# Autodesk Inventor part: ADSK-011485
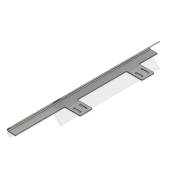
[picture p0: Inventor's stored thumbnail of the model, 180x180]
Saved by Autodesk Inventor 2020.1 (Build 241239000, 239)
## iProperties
Created: 2000-01
Part Number: ADSK-011485
Material: 1.0312 DC05
Description: FSHTPH,SS,CP,01,038,019,230,135,PLOW,END_TAB
Document SubType Name: Tôlerie
Designer: sspink
Density: 1 g/cm^3
Sheet Metal Rule: Stahlblech 1.0312 - DC05 -   3.0 mm
Appearance: Stahl
Mass: 159.002 g
Surface Area: 1116.27 cm^2
Volume: 159.002 cm^3
Flat Pattern Width: 58.38 cm
Flat Pattern Length: 15.7693 cm
Flat Pattern Area: 920.615 cm^2
Sheet Metal Width: 583,800 mm
Sheet Metal Length: 157,693 mm
Sheet Metal Area: 92061,453 mm^2
Control State: 0
Master: False
Checked Out: False
Shininess: 57.0
Length Units: 11269
Angle Units: 11279
Time Units: 11290
Mass Units: 11283
Length Display Precision: 3
Angle Display Precision: 2
Compacted: True
CUTLENGTH: 6.20 X 23.00 (143 SI)
MATERIAL DESC: SHEET,S/S, 11 GA
MATERIAL_NUMBER: A084638
G_L: 157,7x583,8 mm
Thickness: 3,000 mm
Dimensions: 97,3x50x583,8 mm
Mass: 0,159 kg
Semi finished: Stahlblech 1.0312 - DC05 -   3.0 mm
Density: 8.03
Volumn: 167.51718721937965
Area: 1115.3407113281999
PropertySet Name: Model Information
Author: sspink
Revision Number: -
Title: FSHTPH,SS,CP,01,038,019,230,135,PLOW,END_TAB
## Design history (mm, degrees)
node "Solide1"
  node "Extrusion1" dims "d2" = 406, "d3" = 0
  node "Extrusion2" dims "d7" = 406 (= d2), "d8" = 0
  node "Fillet1" dims "d9" = 3 (= BendRadius)
  node "Fillet2" dims "d10" = 6 (= 2 x thickness)
  node "Extrusion3" dims "d15" = 63.5, "d16" = 0
  node "Extrusion4" dims "d23" = 50.8, "d24" = 0
  node "Fillet3" dims "d25" = 3.175
  node "Extrusion5" dims "d29" = 177.8, "d30" = 0
sketch "Sketch1"
  geometry: L1 (0, 0)-(35, 0); L2 (35, 0)-(35, 3); L3 (35, 3)-(0, 3); L4 (0, 3)-(0, 0)
  constraints: 8 end point, 2 parallel, 1 horizontal, 1 perpendicular
  dimensions: "d0" = 3 distance between parallel lines of L1 L3 (= thickness); "d1" = 35 distance between parallel lines of L2 L4
sketch "Sketch2"
  geometry: L1 (0, 0)-(0, 3) reference; L2 (0, 3)-(35, 3) reference; L3 (0, 3)-(44.901, 47.901); L4 (44.901, 47.901)-(42.78, 50.023); L5 (42.78, 50.023)-(-7.243, 0); L6 (-7.243, 0)-(0, 0)
  constraints: 8 end point, 2 parallel, 1 perpendicular
  dimensions: "d4" = 3 distance of L3.end L4.end (= thickness); "d5" = 45 deg angle of L2 L3; "d6" = 63.5 distance of L1.end L3.end
workplane "Arbeitsebene5"
workplane "Arbeitsebene6"
workplane "Arbeitsebene7"
workplane "Arbeitsebene4"
workplane "Work Plane3"
node "FlatPattern"
sketch "Sketch3"
  geometry: L1 (0, 3)-(0, 0) reference; L2 (406, 0)-(0, 0) reference; L3 (406, 0)-(406, 3) reference; L4 (406, 3)-(0, 3) reference; L5 (25, 3)-(25, 0); L6 (76, 3)-(76, 0); L7 (279, 3)-(279, 0); L8 (330, 3)-(330, 0)
  constraints: 8 end point, 8 point on line, 3 parallel, 1 perpendicular
  dimensions: "d11" = 76 distance between parallel lines of L8 L3 (= d13); "d12" = 127 distance between parallel lines of L7 L3; "d13" = 76 distance between parallel lines of L6 L1; "d14" = 25 distance between parallel lines of L5 L1
sketch "Sketch4"
  geometry: L1 (91.257, -381)-(91.257, -330) reference; L2 (91.257, -127)-(91.257, -76) reference; L3 (53.757, -371)-(78.757, -371); L4 (78.757, -371)-(78.757, -365); L5 (78.757, -365)-(53.757, -365); L6 (53.757, -365)-(53.757, -371); L7 (78.757, -340)-(53.757, -340); L8 (53.757, -346)-(78.757, -346); L9 (78.757, -346)-(78.757, -340); L10 (53.757, -340)-(53.757, -346); L11 (53.757, -368)-(78.757, -368); L12 (53.757, -343)-(78.757, -343); L13 (66.257, -368)-(66.257, -343); L14 (53.757, -92)-(78.757, -92); L15 (53.757, -89)-(78.757, -89); L16 (78.757, -86)-(53.757, -86); L17 (53.757, -86)-(53.757, -92); L18 (66.257, -114)-(66.257, -89); L19 (78.757, -117)-(78.757, -111); L20 (78.757, -111)-(53.757, -111); L21 (53.757, -117)-(78.757, -117); L22 (53.757, -111)-(53.757, -117); L23 (53.757, -114)-(78.757, -114); L24 (78.757, -92)-(78.757, -86); A1 r 3 centre (53.757, -368) between (53.757, -365) and (53.757, -371); A2 r 3 centre (78.757, -368) between (78.757, -371) and (78.757, -365); A3 r 3 centre (78.757, -343) between (78.757, -346) and (78.757, -340); A4 r 3 centre (53.757, -343) between (53.757, -340) and (53.757, -346); A5 r 3 centre (53.757, -89) between (53.757, -86) and (53.757, -92); A6 r 3 centre (78.757, -89) between (78.757, -92) and (78.757, -86); A7 r 3 centre (78.757, -114) between (78.757, -117) and (78.757, -111); A8 r 3 centre (53.757, -114) between (53.757, -111) and (53.757, -117); 4 further points
  constraints: 44 end point, 16 point on circle, 8 centre point, 8 midpoint, 8 parallel, 8 tangent, 6 horizontal, 6 perpendicular, 2 horizontal alignment, 2 vertical, 2 vertical alignment, 1 collinear
  dimensions: "d17" = 25 distance of L4.end L5.end; "d18" = 6 distance of L3.end L4.end; "d21" = 12.5 distance from line of L11.end L1; "d32" = 25 distance of L7.start L7.end; "d33" = 6 distance of L8.end L7.start; "d34" = 25 distance between parallel lines of L12 L11; "d35" = 25 distance of L19.end L20.end; "d36" = 6 distance of L19.start L19.end; "d37" = 25 distance of L16.start L16.end; "d38" = 6 distance of L14.end L16.start; "d39" = 25 distance between parallel lines of L15 L23
workplane "Work Plane1"
workplane "Work Plane2"
sketch "Sketch5"
  geometry: L1 (7.243, 0)-(35, 0) reference; L2 (35, 3)-(35, 0) reference; L3 (7.243, 3)-(35, 3) reference; L4 (5.121, 8.121)-(44.901, 47.901) reference; L5 (44.901, 47.901)-(42.78, 50.023) reference; L6 (42.78, 50.023)-(3, 10.243) reference; L7 (10.96, 18.203)-(13.081, 16.081); A1 r 6 centre (7.243, 6) between (3, 10.243) and (7.243, 0) reference; A2 r 3 centre (7.243, 6) between (5.121, 8.121) and (7.243, 3) reference
  constraints: 2 end point, 2 point on line, 1 perpendicular
  dimensions: "d28" = 45 distance between parallel lines of L7 L5
node "Corps solides"
node "Corps surfaciques"
feature "Extrusion_mise_à_plat2" dims "d0" = 3 (derived)
other parameters: "thickness" = 3 [user parameter; used in 3 equation terms], "d26" = -25.4, "d27" = -25.4, "d31" = -20.6375, "Thickness" = 3 (derived), "BendRadius" = 3 (= Thickness), "BendReliefWidth" = 3 (= Thickness), "BendReliefDepth" = 1.5 (= 0.5 x Thickness), "CornerReliefSize" = 12 (= 4 x Thickness), "SeamGap" = 0.00508, "MinimumRemnant" = 6 (= 2 x Thickness), "TransitionRadius" = 3 (= BendRadius), "TailleRayonJacobi" = 3 (= BendRadius), "TailleJeu" = 3 (= Thickness)
